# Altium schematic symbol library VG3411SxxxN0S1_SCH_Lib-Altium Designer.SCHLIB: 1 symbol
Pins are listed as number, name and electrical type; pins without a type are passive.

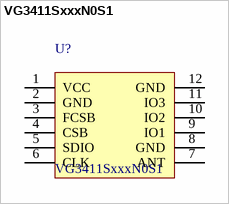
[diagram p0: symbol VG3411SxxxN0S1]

## VG3411SxxxN0S1
designator U?
footprint G3411NS1
footprint G3411NS1-TO
pins: 1 VCC, 2 GND, 3 FCSB, 4 CSB, 5 SDIO, 6 CLK, 7 ANT, 8 GND, 9 IO1, 10 IO2, 11 IO3, 12 GND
